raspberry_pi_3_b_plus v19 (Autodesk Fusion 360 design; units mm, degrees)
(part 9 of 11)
sketch "Sketch2" plane through (0, 10.3, 0) normal (0, 1, 0) x axis (-1, 0, 0)
  line L1 (7.6, 13.37) -> (7.6, 0.37)
  line L2 (-7.6, 13.37) -> (7.6, 13.37)
  line L3 (-7.6, 0.37) -> (-7.6, 13.37)
  line L4 (-6.95, 0.37) -> (-7.6, 0.37)
  line L5 (-6.95, 0.87) -> (-6.95, 0.37)
  line L6 (-6.45, 0.87) -> (-6.95, 0.87)
  line L7 (-6.45, 1.37) -> (-6.45, 0.87)
  line L8 (-6.95, 1.37) -> (-6.45, 1.37)
  line L9 (-6.95, 12.67) -> (-6.95, 1.37)
  line L10 (6.95, 12.67) -> (-6.95, 12.67)
  line L11 (6.95, 1.37) -> (6.95, 12.67)
  line L12 (6.45, 1.37) -> (6.95, 1.37)
  line L13 (6.45, 0.87) -> (6.45, 1.37)
  line L14 (6.95, 0.87) -> (6.45, 0.87)
  line L15 (6.95, 0.37) -> (6.95, 0.87)
  line L16 (7.6, 0.37) -> (6.95, 0.37)
  line L17 (6.95, 0.37) -> (-6.95, 0.37)
  line L18 (-6.45, 2.37) -> (6.45, 2.37)
  line L19 (-6.45, 5.37) -> (-6.45, 2.37)
  line L20 (-6.95, 5.37) -> (-6.45, 5.37)
  line L21 (6.45, 5.37) -> (6.45, 2.37)
  line L22 (6.95, 5.37) -> (6.45, 5.37)
  line L23 (0, 4.9) -> (0, 0)
  point P6 (-6.95, 0.37)
  point P18 (-6.95, 0.37)
  point P17 (6.95, 0.37)
  point P19 (6.95, 0.37)
  point P23 (-6.95, 5.37)
  point P25 (6.95, 5.37)
  point P1 (0, 0)
  point P26 (0, 0)
  point P22 (-6.45, 5.37)
  point P24 (6.45, 5.37)
  coincident P6 P18
  coincident P17 P19
  horizontal L18
  coincident L9 P23
  horizontal L20
  vertical L19
  coincident L11 P25
  vertical L21
  horizontal L22
  coincident P1 P26
  vertical L23
  symmetric P22 P24 L23
  dimension "d391" distance L17 L18 = 2
  dimension "d392" distance P22 P23 = 0.5
  dimension "d393_1" distance L17 L20 = 5
extrude "Extrude3" new body sketch "Sketch2" profile of L5 L6 L7 L8 L9 L11 L12 L13 L14 L15 L17 L18 L19 L20 L21 L22 against normal blind 6 named "d394_1"
combine "Combine1"
work_plane "WorkPlane1" AlongDistance 0.05 (= "sop3_1_above_board") named "d1_2"
sketch "Sketch1" plane through (0, 0, 0.05) normal (0, 0, 1) x axis (1, 0, 0)
  line L1 (-0.8, 0.375) -> (0.8, 0.375)
  line L2 (-0.8, -0.375) -> (-0.8, 0.375)
  line L3 (0.8, -0.375) -> (-0.8, -0.375)
  line L4 (0.8, 0.375) -> (0.8, -0.375)
  line L5 (-0.8, -0.375) -> (0.8, 0.375)
  line L6 (0.8, -0.375) -> (-0.8, 0.375)
  point P6 (0, 0)
  point P1 (0, 0)
  point P4 (-0.8, -0.375)
  point P5 (0.8, -0.375)
  point P3 (-0.8, 0.375)
  perpendicular L1 L2
  parallel L1 L3
  parallel L2 L4
  horizontal L1
  coincident L5 P6
  coincident L6 P6
  coincident P1 P6
  dimension "d2_2" distance P4 P5 = 1.6 (= "sop3_1_package_width")
  dimension "d3_1" distance P3 P4 = 0.75 (= "sop3_1_package_depth")
extrude "Extrude1" new body sketch "Sketch1" profile of L1 L2 L3 L4 along normal blind 0.6 (= "sop3_1_package_height") named "d4_1"
sketch "Sketch2" plane through (0, -0.375, 0) normal (0, -1, 0) x axis (1, 0, 0)
  line L1 (0.8, 0.05) -> (-0.8, 0.05)
  line L2 (0.8, 0.65) -> (0.8, 0.05)
  line L3 (-0.8, 0.65) -> (0.8, 0.65)
  line L4 (-0.8, 0.05) -> (-0.8, 0.65)
  line L5 (-0.1, 0.3) -> (0.1, 0.3)
  line L6 (-0.1, 0.4) -> (-0.1, 0.3)
  line L7 (0.1, 0.4) -> (-0.1, 0.4)
  line L8 (0.1, 0.3) -> (0.1, 0.4)
  line L9 (-0.1, 0.4) -> (0.1, 0.3)
  line L10 (0.1, 0.4) -> (-0.1, 0.3)
  point P10 (0, 0.35)
  point P1 (0, 0)
  point P8 (-0.1, 0.4)
  point P9 (0.1, 0.4)
  point P7 (-0.1, 0.3)
  perpendicular L5 L6
  parallel L5 L7
  parallel L6 L8
  horizontal L5
  coincident L9 P10
  coincident L10 P10
  vertical P1 P10
  dimension "d6_1" distance P8 P9 = 0.2 (= "sop3_1_lead_width")
  dimension "d7_3" distance P7 P8 = 0.1 (= "sop3_1_lead_thickness")
  dimension "d8_4" distance L1 P10 = 0.3 (= "sop3_1_lead_attach")
sketch "Sketch3" plane through (0, 0, 0) normal (1, 0, 0) x axis (0, 1, 0)
  line L1 (-0.425, 0.35) -> (-0.375, 0.35)
  line L2 (-0.525, 0.1635) -> (-0.525, 0.25)
  line L3 (-0.775, 0.05) -> (-0.6163, 0.0639)
  line L4 (-0.375, 0.3) -> (-0.375, 0.4)
  line L5 (-0.225, 0.35) -> (-0.375, 0.35)
  line L6 (-0.275, 0.05) -> (-0.775, 0.05)
  arc A1 centre (-0.425, 0.25) radius 0.1 clockwise from (-0.525, 0.25) to (-0.425, 0.35)
  arc A2 centre (-0.625, 0.1635) radius 0.1 clockwise from (-0.525, 0.1635) to (-0.6163, 0.0639)
  point P2 (-0.375, 0.35)
  point P3 (-0.375, 0.35)
  point P1 (0, 0)
  point P10 (-0.775, 0.05)
  point P13 (-0.225, 0.35)
  point P14 (-0.275, 0.05)
  coincident P2 P3
  tangent L1 A1
  tangent L2 A2
  horizontal L1
  vertical L2
  tangent A1 L2
  horizontal L5
  horizontal L6
  tangent A2 L3
  dimension "d10_2" radius A1 = 0.1 (= "sop3_1_lead_thickness")
  dimension "d11_4" distance P1 P10 = 0.05 (= "sop3_1_lead_thickness / 2")
  dimension "d21_2" distance P3 P13 = 0.15 (= "sop3_1_lead_into_package")
  dimension "d22_3" distance P3 L2 = 0.15 (= "sop3_1_lead_thickness * ( 3 / 2 )")
  dimension "d23_3" distance P3 P10 = 0.4 (= "sop3_1_lead_extension")
  dimension "d24_3" distance P10 P14 = 0.5
  dimension "d25_3" angle L3 L6 = 5 (= "sop3_1_lead_foot_angle")
  dimension "d26_3" radius A2 = 0.1 (= "d10_2")
sweep "Sweep1" sketch "Sketch2" bodies "lead2"
rectangular_pattern "R-Pattern1" uSpaceDistance 0.5 (= "sop3_1_lead_spacing") named "d34_2" vSpaceDistance 0 named "d35_3" bodies "lead1", "lead3"
fillet "Fillet1" radius 0.075 named "d44_4"
move "Move1"
position "Position3"
work_plane "WorkPlane1" AlongDistance 2 named "d121"
sketch "Sketch1" plane through (0, 0, 3.6) normal (0, 0, 1) x axis (1, 0, 0)
  line L1 (-25.3379, 21.238) -> (-35.8379, 21.238)
  line L2 (-25.3379, 8.238) -> (-25.3379, 21.238)
  line L3 (-35.8379, 8.238) -> (-25.3379, 8.238)
  line L4 (-35.8379, 21.238) -> (-35.8379, 8.238)
  point P2 (-35.8379, 21.238)
  point P3 (-25.3379, 21.238)
  point P5 (-35.8379, 8.238)
  horizontal L1
  vertical L2
  horizontal L3
  vertical L4
  dimension "d122" distance P2 P3 = 10.5
  dimension "d167" distance P2 P5 = 13
face "Face1" sketch "Sketch1"
face "EdgeFlange2" FlangeHeight 2 (= "d121") FlangeAngle 90
canvas "Canvas1"
sketch "Sketch1" plane through (0, 0, 0) normal (0, 0, 1) x axis (1, 0, 0)
  line L1 (7.5, 3.5) -> (-7.5, 3.5)
  line L2 (7.5, -3.5) -> (7.5, 3.5)
  line L3 (-7.5, -3.5) -> (7.5, -3.5)
  line L4 (-7.5, 3.5) -> (-7.5, -3.5)
  line L5 (7.5, -3.5) -> (-7.5, 3.5)
  line L6 (-7.5, -3.5) -> (7.5, 3.5)
  line L7 (-5, -3.5) -> (-5, 3.5)
  line L8 (-4.5, -3) -> (-4.5, -3.5)
  line L9 (-1, -3) -> (-4.5, -3)
  line L10 (-1, -3.5) -> (-1, -3)
  line L11 (-3.9058, 0) -> (0, 0)
  line L12 (4.75, -2.75) -> (4.75, -3.5)
  line L13 (6.75, -2.75) -> (4.75, -2.75)
  line L14 (7.5, -0.75) -> (7, -0.75)
  line L15 (3.4, -0.85) -> (4.6, -0.85)
  line L16 (3.4, -1.65) -> (3.4, -0.85)
  line L17 (4.6, -1.65) -> (3.4, -1.65)
  line L18 (4.6, -0.85) -> (4.6, -1.65)
  line L19 (3.4, -1.65) -> (4.6, -0.85)
  line L20 (4.6, -1.65) -> (3.4, -0.85)
  line L21 (3.4, 0.85) -> (4.6, 0.85)
  line L22 (3.4, 1.65) -> (3.4, 0.85)
  line L23 (4.6, 1.65) -> (3.4, 1.65)
  line L24 (4.6, 0.85) -> (4.6, 1.65)
  line L25 (-4.5, 3) -> (-4.5, 3.5)
  line L26 (-1, 3.5) -> (-1, 3)
  line L27 (-1, 3) -> (-4.5, 3)
  line L28 (3.4, 1.65) -> (4.6, 0.85)
  line L29 (3.4, 0.85) -> (4.6, 1.65)
  line L30 (7, 0.75) -> (7.5, 0.75)
  line L31 (7, -0.75) -> (7, 0.75)
  line L32 (6.75, -3) -> (6.75, -2.75)
  line L33 (6.25, -3) -> (6.75, -3)
  line L34 (6.25, -3.5) -> (6.25, -3)
  line L35 (4.75, 2.75) -> (4.75, 3.5)
  line L36 (6.75, 2.75) -> (4.75, 2.75)
  line L37 (6.75, 3) -> (6.75, 2.75)
  line L38 (6.25, 3) -> (6.75, 3)
  line L39 (6.25, 3.5) -> (6.25, 3)
  circle C1 centre (-3, 0) radius 0.5
  circle C2 centre (4, 0) radius 0.5
  point P6 (0, 0)
  point P1 (0, 0)
  point P7 (-5, 3.5)
  point P8 (-5, -3.5)
  point P9 (-4.5, -3.5)
  point P12 (-1, -3.5)
  point P13 (0, 0)
  point P15 (4.75, -3.5)
  point P19 (7.5, -0.75)
  point P24 (4, -1.25)
  point P29 (-4.5, 3.5)
  point P10 (-4.5, -3)
  point P30 (-4.5, 3)
  point P11 (-1, -3)
  point P31 (-1, 3)
  point P32 (-1, 3.5)
  point P20 (4.6, -0.85)
  point P25 (4.6, 0.85)
  point P21 (3.4, -0.85)
  point P26 (3.4, 0.85)
  point P22 (3.4, -1.65)
  point P27 (3.4, 1.65)
  point P23 (4.6, -1.65)
  point P28 (4.6, 1.65)
  point P33 (4, 1.25)
  point P34 (7.5, 0.75)
  point P18 (7, -0.75)
  point P35 (7, 0.75)
  point P36 (-3, 0)
  point P37 (4, 0)
  point P17 (6.25, -3.5)
  point P41 (4.75, 3.5)
  point P16 (4.75, -2.75)
  point P42 (4.75, 2.75)
  point P46 (6.25, 3.5)
  point P38 (6.75, -2.75)
  point P43 (6.75, 2.75)
  point P39 (6.75, -3)
  point P44 (6.75, 3)
  point P40 (6.25, -3)
  point P45 (6.25, 3)
  point P4 (7.5, -3.5)
  point P5 (-7.5, -3.5)
  point P3 (7.5, 3.5)
  perpendicular L1 L2
  parallel L2 L4
  horizontal L1
  coincident L5 P6
  coincident L6 P6
  coincident P1 P6
  coincident L1 P7
  coincident L3 P8
  vertical L7
  coincident L3 P9
  perpendicular L3 L8
  perpendicular L8 L9
  coincident L3 P12
  perpendicular L3 L10
  coincident P1 P13
  horizontal L11
  coincident L3 P15
  perpendicular L3 L12
  perpendicular L12 L13
  coincident L2 P19
  perpendicular L15 L16
  parallel L15 L17
  parallel L16 L18
  horizontal L15
  coincident L19 P24
  coincident L20 P24
  symmetric P9 L11 P29
  symmetric P10 L11 P30
  symmetric P11 L11 P31
  symmetric P12 L11 P32
  symmetric L11 P20 P25
  symmetric L11 P21 P26
  symmetric L11 P22 P27
  symmetric L11 P23 P28
  midpoint L28 P33
  coincident L2 P34
  horizontal L30
  vertical L31
  horizontal L14
  symmetric L11 P18 P35
  coincident L11 P36
  equal C1 C2
  coincident L11 P37
  perpendicular L13 L32
  vertical L34
  horizontal L33
  coincident L3 P17
  symmetric L11 P15 P41
  symmetric L11 P16 P42
  symmetric L11 P17 P46
  symmetric L11 P38 P43
  symmetric L11 P39 P44
  symmetric L11 P40 P45
  dimension "d5_3" distance P4 P5 = 15 (= "pj322_package_length")
  dimension "d6_3" distance P3 P4 = 7 (= "pj322_package_width")
  dimension "d7_5" distance L2 L7 = 12.5
  dimension "d10_6" distance L7 L8 = 0.5
  dimension "d11_8" distance L3 L9 = 0.5
  dimension "d15_4" distance L3 L13 = 0.75
  dimension "d16_6" distance L10 L12 = 5.75
  dimension "d17_6" distance L7 L10 = 4 (= "3.5 mm + ( 1 / 2 ) * 1 mm")
  dimension "d18_8" distance L8 L10 = 3.5
  dimension "d19_6" distance L16 L18 = 1.2
  dimension "d20_6" distance L15 L17 = 0.8
  dimension "d21_6" distance L7 P24 = 9
  dimension "d22_7" distance P24 P33 = 2.5
  dimension "d23_7" distance L14 L30 = 1.5
  dimension "d24_7" diameter C1 = 1
  dimension "d25_7" distance L7 P36 = 2
  dimension "d26_4" distance L7 P37 = 9
  dimension "d27_6" distance L2 L31 = 0.5 (= "d11_8")
  dimension "d187_3" distance L12 L34 = 1.5
  dimension "d188_1" distance L2 L34 = 1.25
  dimension "d189_3" distance L32 L34 = 0.5
  dimension "d190_3" distance L13 L33 = 0.25
extrude "Extrude1" new body sketch "Sketch1" profile of L1 L2 L3 L7 L8 L9 L10 L12 L13 L34 L14 L15 L16 L17 L18 L21 L22 L23 L24 L25 L26 L27 L30 L31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 along normal blind 6 (= "pj322_package_height") named "d8_9"
extrude "Extrude2" cut sketch "Sketch1" profile of L1 L3 L12 L13 L34 L32 L33 L35 L36 L37 L38 L39 along normal blind 4.5 named "d28_6"
extrude "Extrude18" add sketch "Sketch1" profile of C1 C2 against normal blind 1 named "d262_4"
fillet "Fillet2" radius 0.25 named "d264_6"
sketch "Sketch3" plane through (-5, 0, 0) normal (-1, 0, 0) x axis (0, -1, 0)
  line L1 (3.5, 6) -> (3.5, 0)
  line L2 (-3.5, 6) -> (3.5, 6)
  line L3 (-3.5, 0) -> (-3.5, 6)
  line L4 (3.5, 0) -> (-3.5, 0)
  circle C1 centre (0, 3) radius 3
  circle C2 centre (0, 3) radius 1.8
  point P1 (0, 0)
  point P6 (0, 3)
  concentric C1 C2
  vertical P1 P6
  dimension "d57_7" diameter C1 = 6
  dimension "d58_4" diameter C2 = 3.6
extrude "Extrude5" add sketch "Sketch3" profile of C1 C2 along normal blind 2.5 named "d61_6"
extrude "Extrude10" cut sketch "Sketch3" profile of C2 against normal blind 9 named "d99_4" (magnitude of "-12.5 mm + 3.5 mm")
sketch "Sketch2" plane through (0, 0, 6) normal (0, 0, 1) x axis (-1, 0, 0)
  line L1 (5, 0) -> (5, -3.5)
  line L2 (4.5, 3.5) -> (5, 3.5)
  line L3 (4.5, 3) -> (4.5, 3.5)
  line L4 (1, 3) -> (4.5, 3)
  line L5 (1, 3.5) -> (1, 3)
  line L6 (-7.5, 3.5) -> (1, 3.5)
  line L7 (-7.5, -3.5) -> (-7.5, 3.5)
  line L8 (1, -3.5) -> (-7.5, -3.5)
  line L9 (1, -3) -> (1, -3.5)
  line L10 (4.5, -3) -> (1, -3)
  line L11 (4.5, -3.5) -> (4.5, -3)
  line L12 (5, -3.5) -> (4.5, -3.5)
  line L13 (4.5, -1.25) -> (4.5, -2.75)
  line L14 (1.5, -1.25) -> (4.5, -1.25)
  line L15 (1.5, -3) -> (1.5, -1.25)
  line L16 (-0.75, -2.3679) -> (1.5, -2.25)
  line L17 (-0.75, 0.75) -> (-0.75, -2.3679)
  line L18 (1.4, 0.75) -> (-1.5, 0.75)
  line L19 (1.4, 2.75) -> (1.4, 0.75)
  line L20 (-7, 2.5) -> (-7, 3)
  line L21 (-4, 2.5) -> (-7, 2.5)
  line L22 (-1.5, 2.0592) -> (-4, 2.5)
  line L23 (-1.5, 0.75) -> (-1.5, 2.75)
  line L24 (-2, 1.7048) -> (-1.5, 1.7048)
  line L25 (-4, 0.925) -> (-2, 1.7048)
  line L26 (-5.3, 0.925) -> (-4, 0.925)
  line L27 (-5.3, -0.925) -> (-5.3, 0.925)
  line L28 (-4, -0.925) -> (-5.3, -0.925)
  line L29 (-1.75, -1.8) -> (-4, -0.925)
  line L30 (-1, -1.8) -> (-1.75, -1.8)
  line L31 (-1, -2.5) -> (-1, -1.8)
  line L32 (-7, -2.5) -> (-1, -2.5)
  line L33 (-7, -3) -> (-7, -2.5)
  line L34 (-4.1, 0) -> (0, 0)
  line L35 (5, 3.5) -> (5, 0)
  line L36 (-4, -3) -> (-7, -3)
  line L37 (4.5, -2.75) -> (0, -2.75)
  line L38 (-1.5, 2.75) -> (1.4, 2.75)
  line L39 (-7, 3) -> (-4, 3)
  line L40 (0, -2.75) -> (-4, -3)
  line L41 (-1.5, 2.75) -> (-4, 3)
  line L42 (-0.75, -1.8) -> (-1, -1.8)
  line L43 (-4.5, -1.45) -> (-7.5, -1.45)
  line L44 (-4.5, -2.5) -> (-4.5, -1.45)
  line L45 (-7.5, -2.75) -> (-7, -2.75)
  line L46 (-5, 1.45) -> (-7.5, 1.45)
  line L47 (-5, 2.5) -> (-5, 1.45)
  line L48 (-7.5, 2.75) -> (-7, 2.75)
  point P15 (4.5, -2.75)
  point P22 (4.5, -2.75)
  point P1 (0, 0)
  point P37 (0, 0)
  point P31 (-5.3, 0.925)
  point P32 (-5.3, -0.925)
  point P30 (-4, 0.925)
  point P33 (-4, -0.925)
  point P14 (-7, -3)
  point P24 (-7, 3)
  point P25 (-7, 2.5)
  point P36 (-7, -2.5)
  point P12 (4.5, -3)
  point P20 (-0.75, 0.75)
  point P28 (-1.5, 1.7048)
  point P27 (-1.5, 2.0592)
  point P18 (1.5, -2.25)
  point P42 (1.5, -3)
  point P45 (0, -2.75)
  point P43 (-1, -2.5)
  point P44 (-1, -2.5)
  point P48 (-0.75, -1.8)
  point P49 (-7.5, -1.45)
  point P51 (-4.5, -2.5)
  point P52 (-7, -2.75)
  point P53 (-7.5, -2.75)
  point P54 (-7.5, 1.45)
  point P56 (-5, 2.5)
  point P57 (-7, 2.75)
  point P58 (-7.5, 2.75)
  point P17 (1.5, -1.25)
  point P34 (-1.75, -1.8)
  point P26 (-4, 2.5)
  point P29 (-2, 1.7048)
  point P13 (4.5, -3.5)
  point P47 (-4, 3)
  point P46 (-4, -3)
  vertical L13
  horizontal L36
  horizontal L18
  coincident P15 P22
  horizontal L14
  vertical L15
  vertical L17
  vertical L33
  horizontal L32
  vertical L20
  horizontal L38
  horizontal L21
  horizontal L24
  horizontal L26
  vertical L27
  horizontal L28
  vertical L31
  vertical L23
  vertical L19
  coincident P1 P37
  horizontal L34
  symmetric P31 P32 L34
  symmetric P30 P33 L34
  symmetric P14 P24 L34
  symmetric P25 P36 L34
  coincident P12 L13
  horizontal L30
  coincident P20 L18
  coincident P28 L23
  coincident P27 L23
  coincident P18 L15
  coincident P42 L36
  horizontal L37
  horizontal L39
  vertical P1 P45
  coincident P43 P44
  coincident L17 P48
  perpendicular L17 L42
  coincident L7 P49
  vertical L44
  coincident L32 P51
  horizontal L43
  coincident L33 P52
  coincident L7 P53
  horizontal L45
  coincident L7 P54
  coincident L21 P56
  vertical L47
  horizontal L46
  coincident L20 P57
  coincident L7 P58
  horizontal L48
  dimension "d30_9" distance L8 L36 = 0.5
  dimension "d31_9" distance L14 L36 = 1.75
  dimension "d32_7" distance P17 P18 = 1
  dimension "d33_7" angle L16 L36 = 3
  dimension "d34_5" distance L7 L27 = 2.2
  dimension "d35_6" distance L7 L33 = 0.5
  dimension "d36_6" distance L32 L36 = 0.5
  dimension "d37_6" distance L18 L38 = 2
  dimension "d38_4" distance L1 L17 = 5.75
  dimension "d39_5" distance L13 L15 = 3
  dimension "d40_6" distance L1 L31 = 6
  dimension "d42_7" distance L26 L28 = 1.85
  dimension "d45_6" distance L7 P34 = 5.75
  dimension "d49_5" distance P32 P33 = 1.3
  dimension "d50_2" distance L1 P27 = 6.5
  dimension "d51_3" angle L21 L22 = 10
  dimension "d53_7" distance L1 L19 = 3.6
  dimension "d54_8" distance P25 P26 = 3
  dimension "d112_5" angle L25 L26 = 21.3
  dimension "d113_5" distance P28 P29 = 0.5
  dimension "d115_4" distance L30 L34 = 1.8 (= "( 3.6 / 2 ) * 1 mm")
  dimension "d116_3" = 21.3
  dimension "d178_3" distance P13 P22 = 0.75
  dimension "d179_4" distance L6 L38 = 0.75
  dimension "d180_3" distance P24 P47 = 3
  dimension "d181_3" distance P14 P46 = 3
  dimension "d192_5" distance L8 L45 = 0.75
  dimension "d193_5" distance L43 L45 = 1.3
  dimension "d194_4" distance L7 L44 = 3
  dimension "d195_4" distance L7 L47 = 2.5
  dimension "d196_3" distance L6 L48 = 0.75 (= "d192_5")
  dimension "d197_3" distance L46 L48 = 1.3 (= "d193_5")
sketch "Sketch4" plane through (0, 0, 6) normal (0, 0, 1) x axis (-1, 0, 0)
  line L1 (5, 0) -> (5, -3.5)
  line L2 (5, 3.5) -> (5, 0)
  line L3 (4.5, 3.5) -> (5, 3.5)
  line L4 (4.5, 3) -> (4.5, 3.5)
  line L5 (1, 3) -> (4.5, 3)
  line L6 (1, 3.5) -> (1, 3)
  line L7 (-7.5, 3.5) -> (1, 3.5)
  line L8 (-7.5, -3.5) -> (-7.5, 3.5)
  line L9 (1, -3.5) -> (-7.5, -3.5)
  line L10 (1, -3) -> (1, -3.5)
  line L11 (4.5, -3) -> (1, -3)
  line L12 (4.5, -3.5) -> (4.5, -3)
  line L13 (5, -3.5) -> (4.5, -3.5)
  line L14 (4.5, 3) -> (4.5, -3)
  line L15 (1, -2.75) -> (1, -3)
  line L16 (-1, -2.75) -> (1, -2.75)
  line L17 (-1, 2.75) -> (-1, -2.75)
  line L18 (1, 2.75) -> (-1, 2.75)
  line L19 (1, 3) -> (1, 2.75)
  line L20 (0, 0) -> (-1, 0)
  point P13 (4.5, -3)
  point P15 (4.5, -3)
  point P6 (4.5, 3)
  point P16 (4.5, 3)
  point P12 (1, -3)
  point P17 (1, -3)
  point P7 (1, 3)
  point P22 (1, 3)
  point P23 (-1, 0)
  point P1 (0, 0)
  point P24 (0, 0)
  coincident P13 P15
  coincident P6 P16
  coincident P12 P17
  perpendicular L11 L15
  perpendicular L15 L16
  perpendicular L11 L17
  perpendicular L17 L18
  coincident P7 P22
  perpendicular L5 L19
  midpoint L17 P23
  coincident P1 P24
  horizontal L20
  dimension "d63_7" distance L9 L16 = 0.75
  dimension "d64_7" distance L1 L17 = 6
extrude "Extrude6" cut sketch "Sketch4" profile of L5 L11 L14 L15 L16 L17 L18 L19 against normal blind 0.75 named "d65_7"
extrude "Extrude3" cut sketch "Sketch2" profile of L37 L13 L14 L15 L16 L17 L18 L19 L39 L20 L21 L22 L23 L31 L32 L33 L40 L41 L42 against normal blind 4.5 named "d55_7"
extrude "Extrude7" cut sketch "Sketch2" profile of L17 L18 L23 L24 L25 L26 L27 L28 L29 L30 L42 against normal blind 3 named "d67_7"
extrude "Extrude17" cut sketch "Sketch2" profile of L7 L20 L21 L32 L33 L43 L44 L45 L46 L47 L48 against normal blind 0.3 named "d198_2"
sketch "Sketch5" plane through (7.5, 0, 0) normal (1, 0, 0) x axis (0, 1, 0)
  line L1 (3.5, 0) -> (-3.5, 0)
  line L2 (3.5, 6) -> (3.5, 0)
  line L3 (-3.5, 6) -> (-2.75, 6)
  line L4 (-3.5, 0) -> (-3.5, 6)
  line L5 (0, 3) -> (0, 0)
  line L6 (1, 1.3) -> (1, 0.5)
  line L7 (0.75, 1.701) -> (0.75, 1.3)
  line L8 (1.25, 1.3) -> (1.25, 0)
  line L9 (0.5, 1) -> (-0.5, 1)
  line L10 (0.5, 1.5858) -> (0.5, 1)
  line L11 (0.5, 0) -> (0.5, 0.5)
  line L12 (1.25, 0.8) -> (1, 0.8)
  line L13 (1.25, 1.3) -> (0.75, 1.3)
  line L14 (-1.25, 1.3) -> (-1.25, 0)
  line L15 (-1.25, 1.3) -> (-0.75, 1.3)
  line L16 (-0.75, 1.701) -> (-0.75, 1.3)
  line L17 (-1.25, 0.8) -> (-1, 0.8)
  line L18 (-1, 1.3) -> (-1, 0.5)
  line L19 (-0.5, 0) -> (-0.5, 0.5)
  line L20 (-0.5, 1.5858) -> (-0.5, 1)
  line L21 (1.25, 0.5) -> (-1.25, 0.5)
  line L22 (-1.45, 5.7) -> (-1.45, 6)
  line L23 (-2.75, 5.7) -> (-1.45, 5.7)
  line L24 (-2.75, 6) -> (-2.75, 5.7)
  line L25 (2.75, 6) -> (3.5, 6)
  line L26 (2.75, 5.7) -> (2.75, 6)
  line L27 (1.45, 5.7) -> (2.75, 5.7)
  line L28 (1.45, 6) -> (1.45, 5.7)
  line L29 (-1.45, 6) -> (1.45, 6)
  circle C1 centre (0, 3) radius 1.5
  point P1 (0, 0)
  point P7 (0, 0)
  point P12 (1.25, 0)
  point P19 (0.5, 0)
  point P6 (0, 3)
  point P10 (0.75, 1.701)
  point P17 (0.5, 1.5858)
  point P20 (1, 0.8)
  point P21 (1.25, 0.8)
  point P11 (1, 1.3)
  point P9 (0.75, 1.3)
  point P24 (-0.75, 1.3)
  point P25 (-0.75, 1.701)
  point P29 (-1, 1.3)
  point P22 (-1.25, 0)
  point P13 (1.25, 1.3)
  point P23 (-1.25, 1.3)
  point P14 (1, 0.5)
  point P28 (-1, 0.5)
  point P16 (0.5, 1)
  point P32 (-0.5, 1)
  point P33 (-0.5, 1.5858)
  point P18 (0.5, 0.5)
  point P30 (-0.5, 0.5)
  point P31 (-0.5, 0)
  point P26 (-1, 0.8)
  point P27 (-1.25, 0.8)
  point P15 (-0.5, 1)
  point P8 (0, 3)
  point P34 (1.25, 0.5)
  point P35 (-1.25, 0.5)
  coincident P1 P7
  vertical L5
  vertical L7
  vertical L6
  vertical L8
  coincident L1 P12
  vertical L10
  horizontal L9
  coincident L1 P19
  vertical L11
  coincident P6 L5
  coincident C1 P10
  coincident C1 P17
  coincident L6 P20
  coincident L8 P21
  horizontal L12
  coincident P11 L13
  symmetric L5 P9 P24
  symmetric L5 P10 P25
  symmetric L5 P11 P29
  symmetric L5 P12 P22
  symmetric L5 P13 P23
  symmetric L5 P14 P28
  symmetric L5 P16 P32
  symmetric L5 P17 P33
  symmetric L5 P18 P30
  symmetric L5 P19 P31
  symmetric L5 P20 P26
  symmetric L5 P21 P27
  coincident P15 P32
  coincident P18 L21
  coincident P6 P8
  horizontal L13
  coincident L8 P34
  coincident P14 L21
  coincident L14 P35
  coincident P28 L21
  dimension "d70_4" diameter C1 = 3
  dimension "d100_1" distance L1 P6 = 3
  dimension "d102_4" distance P12 L13 = 1.3
  dimension "d104_5" distance L1 L21 = 0.5
  dimension "d105_4" distance L6 L18 = 2
  dimension "d106_3" distance L10 L20 = 1
  dimension "d107_5" distance P6 L9 = 2
  dimension "d108_5" distance L8 L14 = 2.5
  dimension "d109_2" distance L11 L19 = 1
  dimension "d110_3" distance L12 L21 = 0.3
  dimension "d111_5" distance L7 L16 = 1.5
extrude "Extrude11" cut sketch "Sketch5" profile of C1 L6 L7 L9 L10 L13 L15 L16 L18 L20 L21 against normal blind 12 named "d83_6"
extrude "Extrude8" cut sketch "Sketch5" profile of C1 against normal blind 3.5 named "d71_3"
extrude "Extrude12" cut sketch "Sketch5" profile of C1 L9 L10 L20 against normal blind 13.5 named "d87_5"
fillet "Fillet1" radius 0.5 named "d90_5"
chamfer "Chamfer2" distance 0.2 named "d91_6"
extrude "Extrude13" cut sketch "Sketch5" profile of L6 L8 L12 L14 L17 L18 L21 against normal blind 3 named "d92_7"
extrude "Extrude14" cut sketch "Sketch5" profile of L1 L11 L19 L21 against normal blind 0.5 named "d95_3"
extrude "Extrude15" cut sketch "Sketch5" profile of L1 L8 L11 L14 L19 L21 against normal blind 0.25 named "d97_3"
chamfer "Chamfer3" distance 0.5 named "d117_2" distance 0.3 named "d118_3"
work_plane "WorkPlane1" AlongDistance 5.25 named "d120_4"
sketch "Sketch1" plane through (0, 0, 5.25) normal (0, 0, 1) x axis (1, 0, 0)
  line L1 (-4.5, 3) -> (-1, 3)
  line L2 (-4.5, -3) -> (-4.5, 3)
  line L3 (-1, -3) -> (-4.5, -3)
  line L4 (-1, 3) -> (-1, -3)
  line L5 (-4.5, -3) -> (-1, 3)
  line L6 (-1, -3) -> (-4.5, 3)
  line L7 (0, 0) -> (-2.75, 0)
  line L8 (-5, 0) -> (-5, 3.5)
  point P6 (-2.75, 0)
  point P7 (-2.75, 0)
  point P1 (0, 0)
  point P8 (0, 0)
  point P3 (-4.5, 3)
  point P4 (-4.5, -3)
  point P5 (-1, -3)
  perpendicular L1 L2
  parallel L1 L3
  parallel L2 L4
  horizontal L1
  coincident L5 P6
  coincident L6 P6
  coincident P6 P7
  coincident P1 P8
  horizontal L7
  dimension "d121_2" distance P3 P4 = 6
  dimension "d122_2" distance P4 P5 = 3.5
  dimension "d124_5" distance L2 L8 = 0.5
face "Face1" sketch "Sketch1"
face "EdgeFlange2" FlangeHeight 5.5 named "d125_4" FlangeAngle 90 named "d126_4" BendRadius 0.25 named "d127_4"
face "EdgeFlange3" EdgeWidth 2 named "d128_5" FlangeHeight 3 named "d129_5" FlangeAngle 10 named "d130_5" BendWidth 0.6 named "d131_5" BendDepth 0.5 named "d132_3" BendRemnant 0 named "d133_5"
face "EdgeFlange4" FlangeHeight 3 named "d134_3" FlangeAngle 20 named "d135_2"
draft "Draft1" Angle1 13 named "d136_2" Angle2 13 named "d137_2"
fillet "Fillet1" radius 0.3 named "d138_2"
face "EdgeFlange5" EdgeOffset_1 0 named "d139_3" EdgeOffset_2 -2.4 named "d140_3" EdgeOffset_1 -2.4 named "d141_4" EdgeOffset_2 0 named "d142_2" FlangeHeight 1 named "d143_3" FlangeAngle 0 named "d144_3"
face "EdgeFlange6" FlangeHeight 1 named "d145_3" FlangeAngle 15 named "d146_2"
face "EdgeFlange7" FlangeHeight 1 named "d147_3" FlangeAngle 30 named "d148_1"
fillet "Fillet2" radius 0.5 named "d149_1"
sketch "Sketch2" plane through (0, -3.35, 0) normal (0, -1, 0) x axis (1, 0, 0)
  line L1 (-1, -0.8078) -> (-2.1, -0.8078)
  line L2 (-1, 5) -> (-1, -0.8078)
  line L3 (-4.5, 5) -> (-1, 5)
  line L4 (-4.5, 0.1) -> (-4.5, 5)
  line L5 (-2.1, 0.1) -> (-4.5, 0.1)
  line L6 (-2.1, -0.8078) -> (-2.1, 0.1)
  line L7 (-3.5, 1.75) -> (-2, 1.75)
  line L8 (-3.5, 3.25) -> (-3.5, 1.75)
  line L9 (-2, 3.25) -> (-3.5, 3.25)
  line L10 (-2, 1.75) -> (-2, 3.25)
  line L11 (-3.5, 3.25) -> (-2, 1.75)
  line L12 (-2, 3.25) -> (-3.5, 1.75)
  line L13 (-1, 0) -> (-4.5, 0)
  point P12 (-2.75, 2.5)
  point P15 (-2.75, 5)
  point P10 (-3.5, 3.25)
  point P11 (-2, 3.25)
  point P9 (-3.5, 1.75)
  perpendicular L7 L8
  parallel L7 L9
  parallel L8 L10
  horizontal L7
  coincident L11 P12
  coincident L12 P12
  midpoint L3 P15
  vertical P12 P15
  dimension "d150_2" distance P10 P11 = 1.5
  dimension "d151_2" distance P9 P10 = 1.5
  dimension "d153_4" distance P12 L13 = 2.5
extrude "Extrude1" cut sketch "Sketch2" profile of L7 L8 L9 L10 no distance stored
work_plane "WorkPlane1" AlongDistance 0.5 named "d155_1"
sketch "Sketch1" plane through (0, 0, 0.5) normal (0, 0, 1) x axis (1, 0, 0)
  line L1 (4.75, -1.25) -> (7.25, -1.25)
  line L2 (4.75, 1.25) -> (4.75, -1.25)
  line L3 (7.25, 1.25) -> (4.75, 1.25)
  line L4 (7.25, -1.25) -> (7.25, 1.25)
  line L5 (4.75, 1.25) -> (7.25, -1.25)
  line L6 (7.25, 1.25) -> (4.75, -1.25)
  line L7 (6, 0) -> (0, 0)
  line L8 (-5, 0) -> (-5, 3.5)
  point P6 (6, 0)
  point P1 (0, 0)
  point P7 (0, 0)
  point P8 (6, 0)
  point P4 (4.75, 1.25)
  point P5 (7.25, 1.25)
  point P3 (4.75, -1.25)
  perpendicular L1 L2
  parallel L1 L3
  parallel L2 L4
  horizontal L1
  coincident L5 P6
  coincident L6 P6
  coincident P1 P7
  coincident P6 P8
  horizontal L7
  dimension "d156_4" distance P4 P5 = 2.5
  dimension "d157_2" distance P3 P4 = 2.5
  dimension "d158_4" distance P6 L8 = 11
face "Face1" sketch "Sketch1"
face "EdgeFlange2" EdgeWidth 0.5 named "d160_2" FlangeHeight 3.5 named "d161_2" FlangeAngle 90 named "d162_1" BendWidth 0.15 named "d163_1" BendDepth 0.075 named "d164_1" BendRemnant 0 named "d165_2" BendRadius 0.15 named "d166_2"
face "EdgeFlange3" EdgeWidth 1 named "d167_2" FlangeHeight 8.5 named "d168_4" FlangeAngle -3 named "d169_4"
face "EdgeFlange4" EdgeWidth 0.5 named "d170_5" FlangeHeight 1 named "d171_3" FlangeAngle 0 named "d172_3"
face "EdgeFlange5" FlangeHeight 0.8 named "d173_2" FlangeAngle 30 named "d174_3"
face "EdgeFlange6" FlangeHeight 0.8 named "d175_4" FlangeAngle 60 named "d176_3"
extrude "Extrude16" add sketch "Sketch2" profile of L7 L8 L9 L10 against normal blind 0.35 named "d182_3"
draft "Draft1" Angle1 -12 named "d184_3" Angle2 0 named "d185_2"
mirror "Mirror1"
sketch "Sketch1" plane through (0, 0, 1.5) normal (0, 0, 1) x axis (-1, 0, 0)
  line L1 (-6.75, -2.75) -> (-6.75, -3)
  line L2 (-4.75, -2.75) -> (-6.75, -2.75)
  line L3 (-4.75, -3) -> (-4.75, -2.75)
  line L4 (-4, -3) -> (-4.75, -3)
  line L5 (0, -2.75) -> (-4, -3)
  line L6 (4.5, -2.75) -> (0, -2.75)
  line L7 (4.5, -1.25) -> (4.5, -2.75)
  line L8 (1.5, -1.25) -> (4.5, -1.25)
  line L9 (1.5, -2.25) -> (1.5, -1.25)
  line L10 (-0.75, -2.3679) -> (1.5, -2.25)
  line L11 (-0.75, -1.8) -> (-0.75, -2.3679)
  line L12 (-1, -1.8) -> (-0.75, -1.8)
  line L13 (-1, -2.5) -> (-1, -1.8)
  line L14 (-7, -2.5) -> (-1, -2.5)
  line L15 (-7, -3) -> (-7, -2.5)
  line L16 (-6.75, -3) -> (-7, -3)
  line L17 (-3.7, -2.875) -> (-6.95, -2.875)
  line L18 (2.3, -2.3501) -> (-3.7, -2.875)
  line L19 (3.1192, -1.7765) -> (2.3, -2.3501)
  line L20 (3.9383, -2.3501) -> (3.1192, -1.7765)
  point P23 (-6.75, -2.875)
  point P18 (-6.95, -2.875)
  point P19 (-3.7, -2.875)
  point P21 (3.1192, -1.7765)
  point P22 (3.9383, -2.3501)
  point P20 (2.3, -2.3501)
  horizontal L17
  midpoint L1 P23
  coincident L17 P23
  dimension "d205_2" distance L15 P18 = 0.05
  dimension "d206_3" distance P18 P19 = 3.25
  dimension "d207_2" angle L17 L18 = 5
  dimension "d208_5" angle L18 L19 = 30
  dimension "d209_5" angle L19 L20 = 110
  dimension "d210_3" distance P21 P22 = 1
  dimension "d211_1" distance P20 P21 = 1
  dimension "d212_3" distance P19 P20 = 6
face "ContourFlange1" AlongDistance 3 named "d213_3"
face "EdgeFlange2" FlangeHeight 1.2 named "d214_4" FlangeAngle 0 named "d215_4"
face "EdgeFlange3" EdgeOffset_1 0 named "d216_2" EdgeOffset_2 -0.85 named "d217_4" FlangeHeight 1.4 named "d218_5" FlangeAngle 90 named "d219_4" BendWidth 0.4 named "d222_4" BendDepth 0.2 named "d223_5" BendRemnant 0 named "d224_3"
face "EdgeFlange4" FlangeHeight 0.5 named "d220_4" FlangeAngle 0 named "d221_4"
step "Unfold1"
sketch "Sketch2" plane through (0, 0, 5.9) normal (0, 0, 1) x axis (-1, 0, 0)
  line L1 (-6.95, -2.575) -> (-4.5631, -2.575)
  line L2 (-6.95, -3.0274) -> (-6.95, -2.575)
  line L3 (-4.5631, -3.0274) -> (-6.95, -3.0274)
  line L4 (-4.5631, -2.575) -> (-4.5631, -3.0274)
  arc A1 centre (-6.75, -2.8012) radius 0.2262 clockwise from (-6.75, -2.575) to (-6.75, -3.0274)
  point P7 (-6.75, -2.575)
  point P6 (-6.75, -3.0274)
  point P8 (-6.75, -2.8012)
  tangent L3 A1
  coincident L1 P7
  coincident L3 P6
  tangent L1 A1
  dimension "d225_5" distance L2 P8 = 0.2
extrude "Extrude1" cut sketch "Sketch2" profile of L1 L2 L3 A1 no distance stored
step "Refold1"
face "EdgeFlange5" FlangeHeight 4.3 named "d229_5" FlangeAngle 0 named "d230_4" EdgeWidth_1 1.4 named "d231_4" EdgeWidth_2 -0.4 named "d232_5"
sketch "Sketch1" plane through (0, 0, 1.5) normal (0, 0, 1) x axis (-1, 0, 0)
  line L1 (1.4, 0.995) -> (-1.5, 0.995)
  line L2 (1.4, 2.75) -> (1.4, 0.995)
  line L3 (-1.5, 2.75) -> (1.4, 2.75)
  line L4 (-4, 3) -> (-1.5, 2.75)
  line L5 (-4.75, 3) -> (-4, 3)
  line L6 (-4.75, 2.75) -> (-4.75, 3)
  line L7 (-6.75, 2.75) -> (-4.75, 2.75)
  line L8 (-6.75, 3) -> (-6.75, 2.75)
  line L9 (-7, 3) -> (-6.75, 3)
  line L10 (-7, 2.5) -> (-7, 3)
  line L11 (-4, 2.5) -> (-7, 2.5)
  line L12 (-1.5, 2.0592) -> (-4, 2.5)
  line L13 (-1.5, 0.995) -> (-1.5, 2.0592)
  line L14 (-3.95, 2.875) -> (-6.95, 2.875)
  line L15 (-0.95, 2.2373) -> (-3.95, 2.875)
  line L16 (-0.2069, 1.5682) -> (-0.95, 2.2373)
  line L17 (0.7442, 1.8772) -> (-0.2069, 1.5682)
  point P20 (-6.75, 2.875)
  point P15 (-6.95, 2.875)
  point P16 (-3.95, 2.875)
  point P17 (-0.95, 2.2373)
  point P18 (-0.2069, 1.5682)
  point P19 (0.7442, 1.8772)
  midpoint L8 P20
  coincident L14 P20
  horizontal L14
  dimension "d233_5" distance L10 P15 = 0.05
  dimension "d234_5" distance P15 P16 = 3
  dimension "d235_5" distance P16 P17 = 3
  dimension "d236_5" angle L15 L16 = 30
  dimension "d237_5" angle L16 L17 = 120
  dimension "d238_3" angle L14 L15 = 12
  dimension "d239_3" distance P17 P18 = 1
  dimension "d240_5" distance P18 P19 = 1
face "ContourFlange1" AlongDistance 3 named "d241_4"
face "EdgeFlange2" FlangeHeight 1.2 named "d242_5" FlangeAngle 0 named "d243_4"
face "EdgeFlange3" EdgeWidth_1 0.45 named "d244_5" EdgeWidth_2 1.4842 named "d245_5" FlangeHeight 1.5 named "d246_3" FlangeAngle 90 named "d247_3" BendWidth 0.4 named "d248_3" BendDepth 0.2 named "d249_2" BendRemnant 0 named "d250_3"
face "EdgeFlange4" FlangeHeight 0.5 named "d251_2" FlangeAngle 0 named "d252_3"
step "Unfold1"
sketch "Sketch2" plane through (0, 0, 5.9) normal (0, 0, 1) x axis (-1, 0, 0)
  line L1 (-5.0158, 2.575) -> (-6.95, 2.575)
  line L2 (-5.0158, 3.0274) -> (-5.0158, 2.575)
  line L3 (-6.95, 3.0274) -> (-5.0158, 3.0274)
  line L4 (-6.95, 2.575) -> (-6.95, 3.0274)
  arc A1 centre (-6.7, 2.8012) radius 0.2262 clockwise from (-6.7, 3.0274) to (-6.7, 2.575)
  point P7 (-6.7, 3.0274)
  point P6 (-6.7, 2.575)
  point P8 (-6.7, 2.8012)
  tangent L1 A1
  coincident L3 P7
  coincident L1 P6
  tangent L3 A1
  dimension "d253_2" distance L4 P8 = 0.25
extrude "Extrude1" cut sketch "Sketch2" profile of L1 L3 L4 A1 no distance stored
step "Refold1"
face "EdgeFlange5" EdgeWidth_1 -0.25 named "d255_3" EdgeWidth_2 1.25 named "d256_2" FlangeHeight 4.3 named "d257_2" FlangeAngle 0 named "d258_3"
fillet "Fillet1" radius 0.5 named "d259_3"
fillet "Fillet1" radius 0.5 named "d260_5"
fillet "Fillet1" radius 0.5 named "d261_4"
sketch "Sketch1" plane through (0, 0, 1.6) normal (0, 0, 1) x axis (-1, 0, 0)
  line L1 (39.4, 28) -> (39.4, 27.9)
  line L2 (-39.4, 28) -> (39.4, 28)
  line L3 (-39.4, 27.9) -> (-39.4, 28)
  line L4 (-42.5, 24.9) -> (-42.4, 24.9)
  line L5 (-42.5, -24.9) -> (-42.5, 24.9)
  line L6 (-42.4, -24.9) -> (-42.5, -24.9)
  line L7 (-39.4, -28) -> (-39.4, -27.9)
  line L8 (39.4, -28) -> (-39.4, -28)
  line L9 (39.4, -27.9) -> (39.4, -28)
  line L10 (42.5, -24.9) -> (42.4, -24.9)
  line L11 (42.5, 24.9) -> (42.5, -24.9)
  line L12 (42.4, 24.9) -> (42.5, 24.9)
  circle C1 centre (1.11, -25.52) radius 0.5
  circle C2 centre (3.65, -25.52) radius 0.5
  circle C3 centre (6.19, -25.52) radius 0.5
  circle C4 centre (8.73, -25.52) radius 0.5
  circle C5 centre (11.27, -25.52) radius 0.5
  circle C6 centre (13.81, -25.52) radius 0.5
  circle C7 centre (16.35, -25.52) radius 0.5
  circle C8 centre (18.89, -25.52) radius 0.5
  circle C9 centre (-1.43, -25.52) radius 0.5
  circle C10 centre (-3.97, -25.52) radius 0.5
  circle C11 centre (-6.51, -25.52) radius 0.5
  circle C12 centre (-9.05, -25.52) radius 0.5
  circle C13 centre (-11.59, -25.52) radius 0.5
  circle C14 centre (-14.13, -25.52) radius 0.5
  circle C15 centre (6.19, -22.98) radius 0.5
  circle C16 centre (3.65, -22.98) radius 0.5
  circle C17 centre (-1.43, -22.98) radius 0.5
  circle C18 centre (-3.97, -22.98) radius 0.5
  circle C19 centre (-6.51, -22.98) radius 0.5
  circle C20 centre (-9.05, -22.98) radius 0.5
  circle C21 centre (-11.59, -22.98) radius 0.5
  circle C22 centre (-14.13, -22.98) radius 0.5
  circle C23 centre (34.13, -25.52) radius 0.5
  circle C24 centre (31.59, -25.52) radius 0.5
  circle C25 centre (29.05, -25.52) radius 0.5
  circle C26 centre (26.51, -25.52) radius 0.5
  circle C27 centre (23.97, -25.52) radius 0.5
  circle C28 centre (21.43, -25.52) radius 0.5
  circle C29 centre (8.73, -22.98) radius 0.5
  circle C30 centre (11.27, -22.98) radius 0.5
  circle C31 centre (13.81, -22.98) radius 0.5
  circle C32 centre (16.35, -22.98) radius 0.5
  circle C33 centre (18.89, -22.98) radius 0.5
  circle C34 centre (21.43, -22.98) radius 0.5
  circle C35 centre (23.97, -22.98) radius 0.5
  circle C36 centre (26.51, -22.98) radius 0.5
  circle C37 centre (29.05, -22.98) radius 0.5
  circle C38 centre (31.59, -22.98) radius 0.5
  circle C39 centre (34.13, -22.98) radius 0.5
  circle C40 centre (-17.73, -17.107) radius 0.5
  circle C41 centre (-20.27, -17.107) radius 0.5
  circle C42 centre (-20.27, -19.647) radius 0.5
  circle C43 centre (-17.73, -19.647) radius 0.5
  circle C44 centre (-20.27, -12.01) radius 0.5
  circle C45 centre (-17.73, -12.01) radius 0.5
  circle C46 centre (39, 24.5) radius 1.375
  circle C47 centre (-19, 24.5) radius 1.375
  circle C48 centre (-19, -24.5) radius 1.375
  circle C49 centre (39, -24.5) radius 1.375
  circle C50 centre (1.11, -22.98) radius 0.5
  arc A1 centre (39.4, 24.9) radius 3 clockwise from (39.4, 27.9) to (42.4, 24.9)
  arc A2 centre (-39.4, 24.9) radius 3 clockwise from (-42.4, 24.9) to (-39.4, 27.9)
  arc A3 centre (-39.4, -24.9) radius 3 clockwise from (-39.4, -27.9) to (-42.4, -24.9)
  arc A4 centre (39.4, -24.9) radius 3 clockwise from (42.4, -24.9) to (39.4, -27.9)
sketch "Sketch2" plane through (0, 0, 0) normal (0, 0, -1) x axis (1, 0, 0)
  line L1 (-42.5, 24.9) -> (-42.4, 24.9)
  line L2 (-42.5, -24.9) -> (-42.5, 24.9)
  line L3 (-42.4, -24.9) -> (-42.5, -24.9)
  line L4 (-39.4, -28) -> (-39.4, -27.9)
  line L5 (39.4, -28) -> (-39.4, -28)
  line L6 (39.4, -27.9) -> (39.4, -28)
  line L7 (42.5, -24.9) -> (42.4, -24.9)
  line L8 (42.5, 24.9) -> (42.5, -24.9)
  line L9 (42.4, 24.9) -> (42.5, 24.9)
  line L10 (39.4, 28) -> (39.4, 27.9)
  line L11 (-39.4, 28) -> (39.4, 28)
  line L12 (-39.4, 27.9) -> (-39.4, 28)
  line L13 (11, 19) -> (11, 26.125)
  line L14 (34, 23.5) -> (34, 12)
  line L15 (39.4, -28) -> (-39.4, -28)
  line L16 (-42.5, -24.9) -> (-42.5, 24.9)
  circle C1 centre (-1.11, -25.52) radius 0.5
  circle C2 centre (-3.65, -25.52) radius 0.5
  circle C3 centre (-6.19, -25.52) radius 0.5
  circle C4 centre (-8.73, -25.52) radius 0.5
  circle C5 centre (-11.27, -25.52) radius 0.5
  circle C6 centre (-13.81, -25.52) radius 0.5
  circle C7 centre (-16.35, -25.52) radius 0.5
  circle C8 centre (-18.89, -25.52) radius 0.5
  circle C9 centre (1.43, -25.52) radius 0.5
  circle C10 centre (3.97, -25.52) radius 0.5
  circle C11 centre (6.51, -25.52) radius 0.5
  circle C12 centre (9.05, -25.52) radius 0.5
  circle C13 centre (11.59, -25.52) radius 0.5
  circle C14 centre (14.13, -25.52) radius 0.5
  circle C15 centre (-6.19, -22.98) radius 0.5
  circle C16 centre (-3.65, -22.98) radius 0.5
  circle C17 centre (1.43, -22.98) radius 0.5
  circle C18 centre (3.97, -22.98) radius 0.5
  circle C19 centre (6.51, -22.98) radius 0.5
  circle C20 centre (9.05, -22.98) radius 0.5
  circle C21 centre (11.59, -22.98) radius 0.5
  circle C22 centre (14.13, -22.98) radius 0.5
  circle C23 centre (-34.13, -25.52) radius 0.5
  circle C24 centre (-31.59, -25.52) radius 0.5
  circle C25 centre (-29.05, -25.52) radius 0.5
  circle C26 centre (-26.51, -25.52) radius 0.5
  circle C27 centre (-23.97, -25.52) radius 0.5
  circle C28 centre (-21.43, -25.52) radius 0.5
  circle C29 centre (-8.73, -22.98) radius 0.5
  circle C30 centre (-11.27, -22.98) radius 0.5
  circle C31 centre (-13.81, -22.98) radius 0.5
  circle C32 centre (-16.35, -22.98) radius 0.5
  circle C33 centre (-18.89, -22.98) radius 0.5
  circle C34 centre (-21.43, -22.98) radius 0.5
  circle C35 centre (-23.97, -22.98) radius 0.5
  circle C36 centre (-26.51, -22.98) radius 0.5
  circle C37 centre (-29.05, -22.98) radius 0.5
  circle C38 centre (-31.59, -22.98) radius 0.5
  circle C39 centre (-34.13, -22.98) radius 0.5
  circle C40 centre (17.73, -17.107) radius 0.5
  circle C41 centre (20.27, -17.107) radius 0.5
  circle C42 centre (20.27, -19.647) radius 0.5
  circle C43 centre (17.73, -19.647) radius 0.5
  circle C44 centre (20.27, -12.01) radius 0.5
  circle C45 centre (17.73, -12.01) radius 0.5
  circle C46 centre (-39, 24.5) radius 1.375
  circle C47 centre (19, 24.5) radius 1.375
  circle C48 centre (19, -24.5) radius 1.375
  circle C49 centre (-39, -24.5) radius 1.375
  circle C50 centre (-1.11, -22.98) radius 0.5
  arc A1 centre (-39.4, 24.9) radius 3 clockwise from (-42.4, 24.9) to (-39.4, 27.9)
  arc A2 centre (-39.4, -24.9) radius 3 clockwise from (-39.4, -27.9) to (-42.4, -24.9)
  arc A3 centre (39.4, -24.9) radius 3 clockwise from (42.4, -24.9) to (39.4, -27.9)
  arc A4 centre (39.4, 24.9) radius 3 clockwise from (39.4, 27.9) to (42.4, 24.9)
  circle C51 centre (11, 26.125) radius 0.6
  circle C52 centre (11, 19) radius 0.6
  circle C53 centre (34, 23.5) radius 1.75
  circle C54 centre (34, 12) radius 1.75
  circle C55 centre (-34.3, -8.25) radius 0.5
  circle C56 centre (-27.0471, -21.25) radius 0.5
  point P72 (11, 26.125)
  point P74 (11, 26.125)
  point P73 (11, 19)
  point P75 (11, 19)
  point P76 (11, 21.75)
  point P78 (34, 12)
  point P79 (34, 12)
  point P77 (34, 23.5)
  point P80 (34, 23.5)
  point P81 (34, 17.75)
  point P82 (-34.3, -8.25)
  point P86 (-39, -24.5)
  point P83 (-27.0471, -21.25)
  coincident P72 P74
  coincident P73 P75
  vertical L13
  coincident L13 P76
  equal C53 C54
  coincident P78 P79
  coincident P77 P80
  vertical L14
  coincident L14 P81
  midpoint L14 P81
  dimension "d262" diameter C51 = 1.2
  dimension "d263" diameter C52 = 1.2
  dimension "d285" distance P73 P76 = 2.75
  dimension "d287" distance P72 P73 = 7.125
  dimension "d291" diameter C53 = 3.5
  dimension "d297" distance P79 P80 = 11.5
  dimension "d301" diameter C55 = 1
  dimension "d307" diameter C56 = 1
  dimension "d319" distance P82 P86 = 16.25
  dimension "d331" distance P82 L16 = 8.2
  dimension "d332" distance P83 P86 = 3.25
  dimension "d348" distance P83 L16 = 15.4529
extrude "Extrude2" cut sketch "Sketch2" profile of C51 C52 C53 C54 C55 C56 against normal blind 2
base_feature "Base Feature1"
sketch "Sketch1" plane through (0, 0, 0) normal (0, 1, 0) x axis (1, 0, 0)
  line L1 (6.7, -5.73) -> (-6.7, -5.73)
  line L2 (7, -2.9561) -> (7, -5.43)
  line L3 (6.1703, -2.4745) -> (6.7902, -2.67)
  line L4 (5.0096, -1.2812) -> (5.9238, -2.3144)
  line L5 (0, -8.8014) -> (0, 0)
  line L6 (-7, -2.9561) -> (-7, -5.43)
  line L7 (-6.1703, -2.4745) -> (-6.7902, -2.67)
  line L8 (-5.0096, -1.2812) -> (-5.9238, -2.3144)
  line L9 (0.45, -1.18) -> (4.785, -1.18)
  line L10 (-4.785, -1.18) -> (0.4, -1.18)
  arc A1 centre (6.7, -5.43) radius 0.3 clockwise from (7, -5.43) to (6.7, -5.73)
  arc A2 centre (6.7, -2.9561) radius 0.3 clockwise from (6.7902, -2.67) to (7, -2.9561)
  arc A3 centre (6.3357, -1.95) radius 0.55 clockwise from (6.1703, -2.4745) to (5.9238, -2.3144)
  arc A4 centre (4.785, -1.48) radius 0.3 clockwise from (4.785, -1.18) to (5.0096, -1.2812)
  arc A5 centre (-6.7, -5.43) radius 0.3 clockwise from (-6.7, -5.73) to (-7, -5.43)
  arc A6 centre (-6.7, -2.9561) radius 0.3 clockwise from (-7, -2.9561) to (-6.7902, -2.67)
  arc A7 centre (-6.3357, -1.95) radius 0.55 clockwise from (-5.9238, -2.3144) to (-6.1703, -2.4745)
  arc A8 centre (-4.785, -1.48) radius 0.3 clockwise from (-5.0096, -1.2812) to (-4.785, -1.18)
  point P1 (0, 0)
  point P16 (0, 0)
  point P3 (6.7, -5.73)
  point P19 (-6.7, -5.73)
  point P4 (7, -5.43)
  point P20 (-7, -5.43)
  point P6 (7, -2.9561)
  point P21 (-7, -2.9561)
  point P7 (6.7902, -2.67)
  point P23 (-6.7902, -2.67)
  point P9 (6.1703, -2.4745)
  point P24 (-6.1703, -2.4745)
  point P10 (5.9238, -2.3144)
  point P26 (-5.9238, -2.3144)
  point P12 (5.0096, -1.2812)
  point P27 (-5.0096, -1.2812)
  point P13 (4.785, -1.18)
  point P29 (-4.785, -1.18)
  point P15 (-4.785, -1.18)
  point P2 (-6.7, -5.73)
  point P30 (0.4, -1.18)
  point P31 (0.45, -1.18)
  horizontal L1
  tangent L1 A1
  vertical L2
  tangent L2 A2
  tangent A2 L3
  tangent L3 A3
  tangent A3 L4
  tangent L4 A4
  horizontal L9
  coincident P1 P16
  vertical L5
  tangent A4 L9
  tangent A1 L2
  symmetric P3 L5 P19
  symmetric P4 L5 P20
  symmetric A1 L5 A5
  symmetric P6 L5 P21
  symmetric P7 L5 P23
  symmetric A2 L5 A6
  symmetric P9 L5 P24
  symmetric P10 L5 P26
  symmetric A3 L5 A7
  symmetric P12 L5 P27
  symmetric P13 L5 P29
  symmetric A4 L5 A8
  coincident P15 P29
  coincident P2 P19
  coincident P30 L9
  collinear L9 L10
  dimension "d2_6" radius A1 = 0.3
  dimension "d3_5" radius A2 = 0.3
  dimension "d4_5" radius A4 = 0.3
  dimension "d5_4" radius A3 = 0.55
  dimension "d6_4" distance L2 L6 = 14
  dimension "d7_6" distance P7 P9 = 0.65
  dimension "d8_10" angle L2 L3 = 107.5
  dimension "d9_5" angle L4 L9 = 131.5
  dimension "d11_9" distance L1 L9 = 4.55
  dimension "d12_3" distance P1 L9 = 1.18
  dimension "d16_7" distance L1 P7 = 3.06
  dimension "d17_7" distance P30 P31 = 0.05
  dimension "d19_7" distance L5 P30 = 0.4
face "ContourFlange1" AlongDistance 5.775 (= "( 11.55 / 2 ) * 1 mm") named "d18_9"
step "Unfold1"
